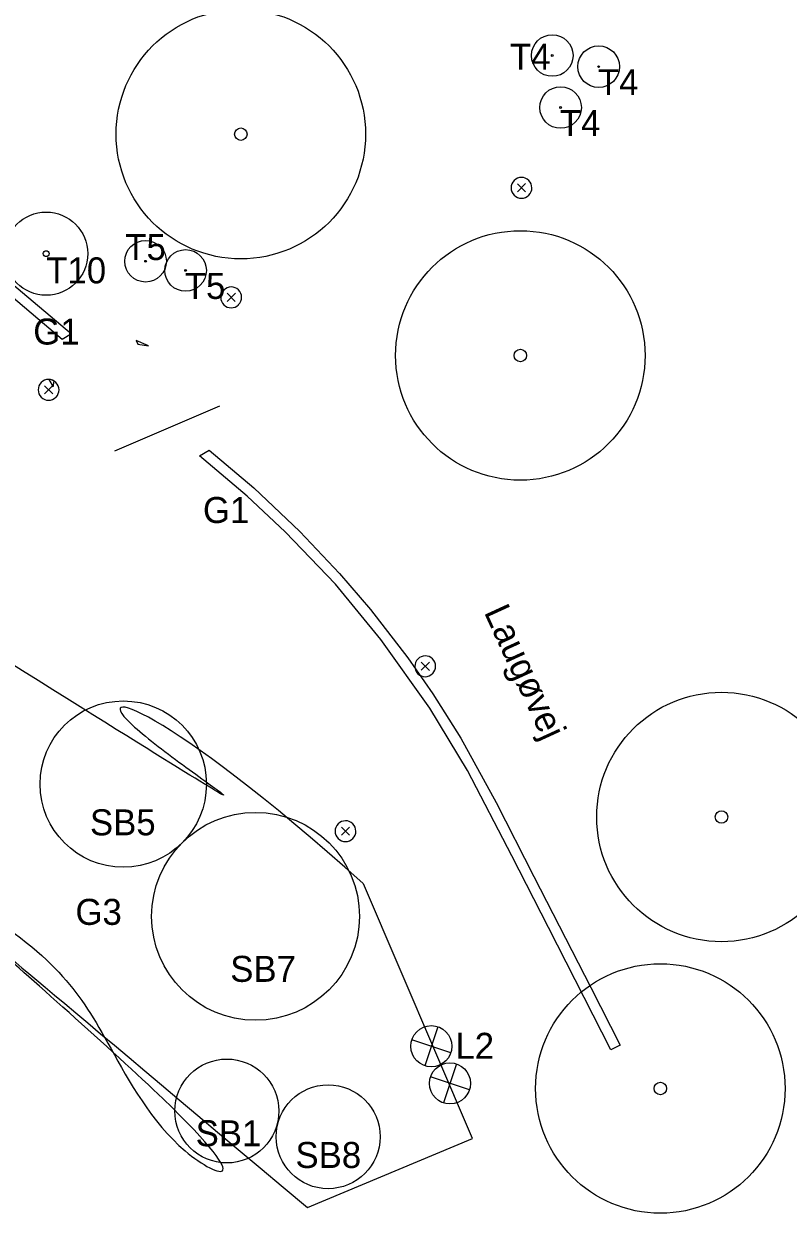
# Model space of a CAD drawing. Extents: x 0 to 512122, y 0 to 6212554.
# Drawn here: x 511767.6 to 511804.4, y 6211767.9 to 6211825.1 of the extents above; entities that cross this region are included whole.
import ezdxf

# ---------------------------------------------------------------- set-up
doc = ezdxf.new("R2010")
doc.units = 0
for name, color, linetype in [('_Fjernes træer', 7, 'Continuous'), ('_lights', 7, 'Continuous'), ('_Låge L2', 7, 'Continuous'), ('L40 jord udlagt muld og grøft', 7, 'Continuous'), ('MatrikelnummerMaster', 7, 'Continuous'), ('Skel', 7, 'Continuous'), ('TV_U_AFM_Symbl_Gul', 7, 'Continuous'), ('TV_U_LYS_Ledn-', 7, 'Continuous'), ('TV_U_LYS_Mastenummer', 7, 'Continuous')]:
    doc.layers.add(name, color=color, linetype=linetype)

# ---------------------------------------------------------------- blocks, each defined once
blk = doc.blocks.new('SOLITAIRE TREES')
at = {"layer": 'Skel'}
for radius in [2, 0.141]:
    blk.add_circle((0, 0), radius, dxfattribs=at)
blk = doc.blocks.new('fruittrees')
at = {"layer": 'TV_U_LYS_Ledn-'}
blk.add_circle((0, 0), 1, dxfattribs=at)
at = {"layer": 'TV_U_LYS_Mastenummer'}
blk.add_circle((0, 0), 0.0426, dxfattribs=at)

msp = doc.modelspace()

# ---------------------------------------------------------------- linework, layer by layer
at = {"layer": '_Fjernes træer'}
for centre, radius in [((511778.083, 6211819.836), 6), ((511778.083, 6211819.836), 0.3), ((511791.527, 6211809.191), 6), ((511791.527, 6211809.191), 0.3), ((511801.2, 6211786.991), 6), ((511801.2, 6211786.991), 0.3), ((511798.261, 6211773.931), 6), ((511798.261, 6211773.931), 0.3)]:
    msp.add_circle(centre, radius, dxfattribs=at)
at = {"layer": '_lights'}
for p, q in [((511791.384, 6211817.451), (511791.778, 6211817.057)), ((511791.782, 6211817.455), (511791.388, 6211817.061)), ((511777.421, 6211812.183), (511777.816, 6211811.788)), ((511777.819, 6211812.186), (511777.425, 6211811.792)), ((511768.639, 6211807.734), (511769.033, 6211807.34)), ((511769.037, 6211807.738), (511768.643, 6211807.344)), ((511786.756, 6211794.435), (511787.15, 6211794.041)), ((511787.154, 6211794.439), (511786.76, 6211794.045)), ((511782.917, 6211786.503), (511783.312, 6211786.109)), ((511783.316, 6211786.507), (511782.921, 6211786.113))]:
    msp.add_line(p, q, dxfattribs=at)
for centre, start, end in [((511791.581, 6211817.254), 315.5636, 315), ((511791.581, 6211817.254), 315, 315.5636), ((511777.618, 6211811.985), 315.5636, 315), ((511777.618, 6211811.985), 315, 315.5636), ((511768.836, 6211807.537), 315.5636, 315), ((511768.836, 6211807.537), 315, 315.5636), ((511786.953, 6211794.238), 315.5636, 315), ((511786.953, 6211794.238), 315, 315.5636), ((511783.115, 6211786.306), 315.5636, 315), ((511783.115, 6211786.306), 315, 315.5636)]:
    msp.add_arc(centre, 0.5, start, end, dxfattribs=at)
at = {"layer": '_Låge L2'}
for p, q in [((511787.561, 6211776.902), (511786.935, 6211775.026)), ((511788.186, 6211775.651), (511786.31, 6211776.276)), ((511788.454, 6211775.112), (511787.828, 6211773.236)), ((511789.079, 6211773.861), (511787.203, 6211774.487))]:
    msp.add_line(p, q, dxfattribs=at)
for centre in [(511787.248, 6211775.964), (511788.141, 6211774.174)]:
    msp.add_circle(centre, 0.989, dxfattribs=at)
at = {"layer": 'L40 jord udlagt muld og grøft'}
for p, q in [((511773.647, 6211809.646), (511773.055, 6211809.91)), ((511773.055, 6211809.91), (511773.131, 6211809.728)), ((511773.131, 6211809.728), (511773.647, 6211809.646)), ((511777.057, 6211806.754), (511771.999, 6211804.593))]:
    msp.add_line(p, q, dxfattribs=at)
for points in [[(511769.935, 6211810.236), (511769.484, 6211809.962), (511766.176, 6211812.76), (511761.976, 6211816.311), (511760.449, 6211817.603), (511758.932, 6211818.906), (511758.06, 6211819.732), (511756.86, 6211821.069), (511756.119, 6211822.019), (511755.556, 6211822.838), (511755.939, 6211823.165), (511756.936, 6211821.763), (511758.212, 6211820.29), (511759.701, 6211818.89), (511762.299, 6211816.693), (511767.069, 6211812.659)], [(511796.331, 6211776.015), (511795.886, 6211775.788), (511792.875, 6211781.671), (511791.111, 6211785.117), (511788.978, 6211789.225), (511787.172, 6211792.223), (511784.823, 6211795.534), (511782.63, 6211798.183), (511780.213, 6211800.714), (511778.385, 6211802.418), (511776.102, 6211804.365), (511776.554, 6211804.638), (511778.703, 6211802.827), (511780.924, 6211800.718), (511782.829, 6211798.709), (511784.315, 6211796.978), (511786.111, 6211794.652), (511787.316, 6211792.918), (511788.658, 6211790.78), (511790.359, 6211787.685), (511792.181, 6211784.125), (511794.914, 6211778.783)]]:
    msp.add_lwpolyline(points, close=True, dxfattribs=at)
msp.add_lwpolyline([(511768.848, 6211808.037), (511769.049, 6211807.682), (511769.102, 6211807.961)], dxfattribs=at)
msp.add_arc((511768.836, 6211807.537), 0.5, 57.9239, 88.6632, dxfattribs=at)
at = {"layer": 'MatrikelnummerMaster'}
msp.add_lwpolyline([(511781.282, 6211768.198), (511789.218, 6211771.532), (511783.975, 6211783.77)], dxfattribs=at)
for points in [[(511783.969, 6211783.784), (511774.35, 6211792.434), (511766.791, 6211794.513), (511783.969, 6211783.784), (511766.791, 6211794.513)], [(511755.899, 6211789.559), (511755.09, 6211788.598), (511755.885, 6211787.544), (511766.013, 6211782.577), (511769.863, 6211779.247), (511771.577, 6211776.373), (511774.889, 6211770.251), (511781.282, 6211768.198), (511755.899, 6211789.559), (511781.282, 6211768.198)]]:
    msp.add_open_spline(points, degree=3, dxfattribs=at)
at = {"layer": 'TV_U_LYS_Mastenummer'}
for centre, radius in [((511772.427, 6211788.574), 4), ((511772.427, 6211788.574), 4), ((511778.79, 6211782.21), 5), ((511778.79, 6211782.21), 5), ((511777.409, 6211772.848), 2.5), ((511782.281, 6211771.611), 2.5), ((511782.281, 6211771.611), 2.5)]:
    msp.add_circle(centre, radius, dxfattribs=at)

# ---------------------------------------------------------------- block references
at = {"layer": 'Skel', "xscale": 0.9999999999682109, "yscale": 0.9999999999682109}
for p in [(511793.062, 6211823.619), (511795.294, 6211823.083), (511793.464, 6211821.117), (511773.5, 6211813.721), (511775.425, 6211813.281)]:
    msp.add_blockref('fruittrees', p, dxfattribs=at)
at = {"layer": 'Skel'}
msp.add_blockref('SOLITAIRE TREES', (511768.719, 6211814.088), dxfattribs=at)

# ---------------------------------------------------------------- texts
at = {"layer": 'TV_U_AFM_Symbl_Gul'}
for s, p in [('T4', (511791.029, 6211822.936)), ('T4', (511795.257, 6211821.712)), ('T4', (511793.427, 6211819.747)), ('T5', (511772.524, 6211813.78)), ('T10', (511768.722, 6211812.659)), ('T5', (511775.387, 6211811.91)), ('G1', (511768.098, 6211809.716)), ('G1', (511776.26, 6211801.132)), ('SB5', (511770.825, 6211786.109)), ('G3', (511770.127, 6211781.801)), ('SB7', (511777.574, 6211779.06)), ('L2', (511788.404, 6211775.358)), ('SB1', (511775.909, 6211771.152)), ('SB8', (511780.711, 6211770.107))]:
    msp.add_text(s, height=1.25, dxfattribs=at).set_placement(p)
msp.add_text('Laugøvej', height=1.25, rotation=294.6577, dxfattribs=at).set_placement((511789.761, 6211796.847))

doc.saveas('drawing.dxf')
